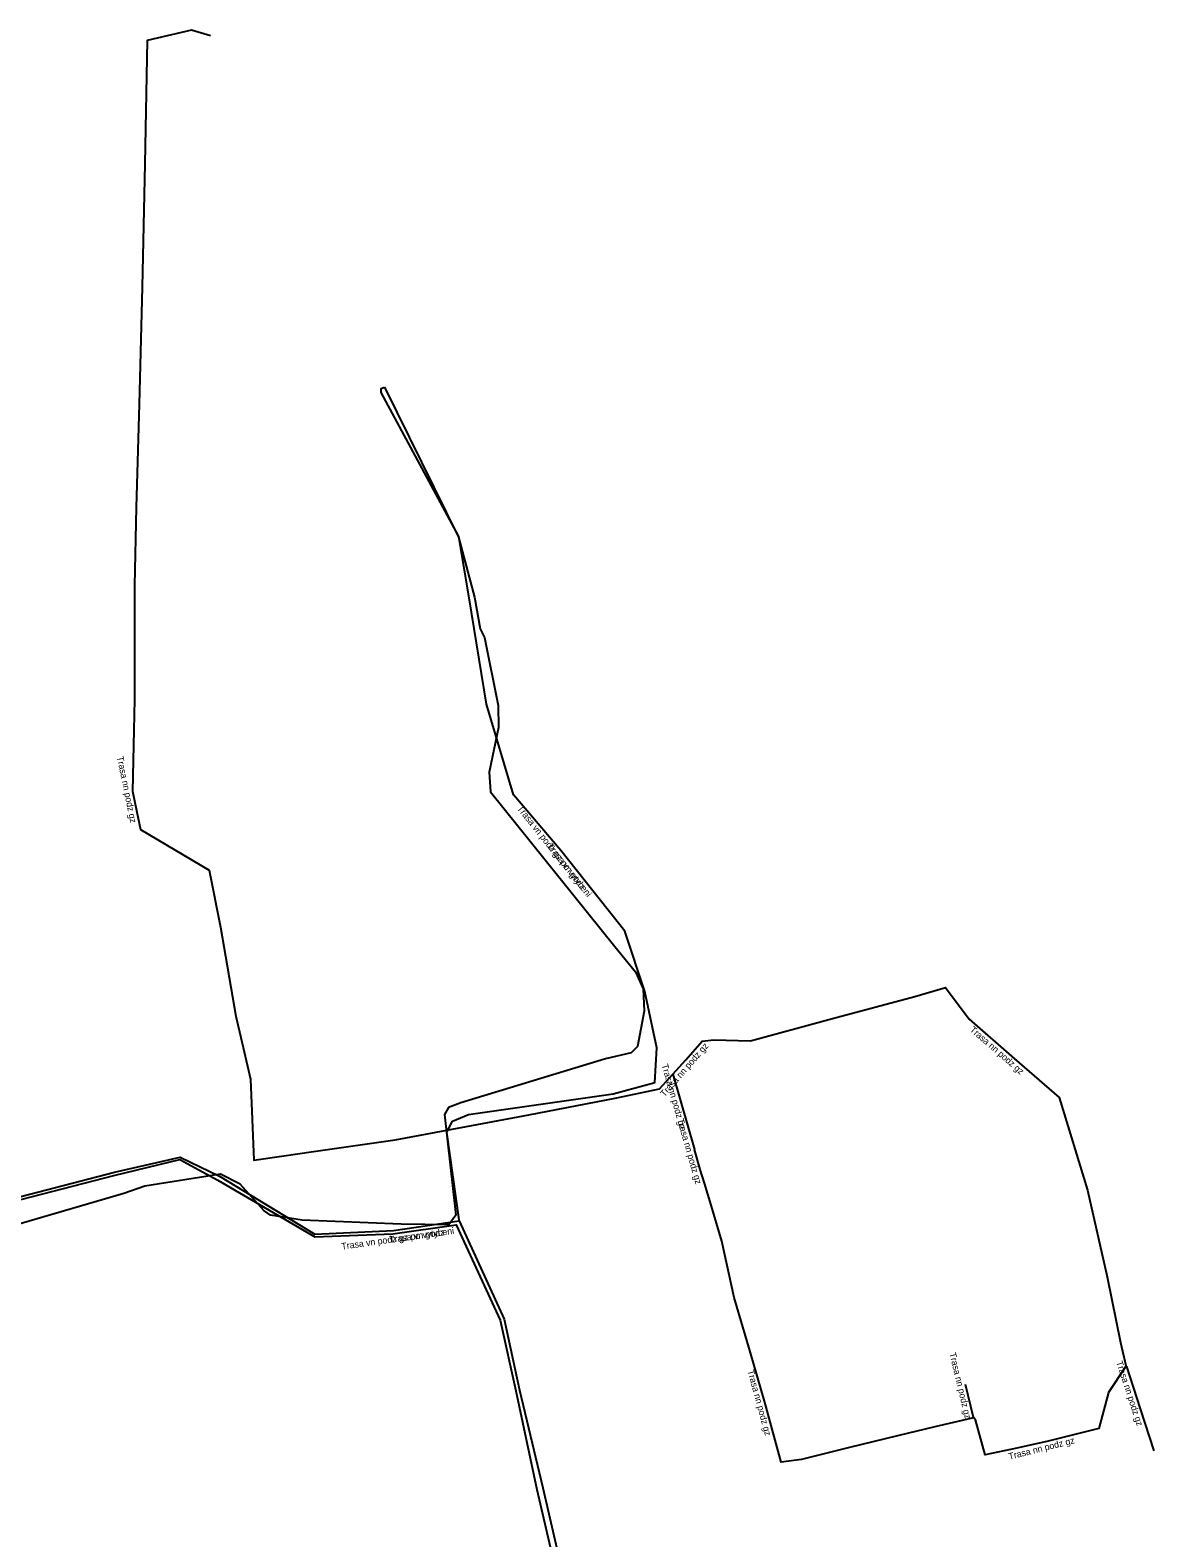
# Model space of a CAD drawing. Extents: x -473162 to -472638, y -1107075 to -1106812.
# Drawn here: x -472955.2 to -472870, y -1106926.5 to -1106811.6 of the extents above; entities that cross this region are included whole.
import ezdxf

# ---------------------------------------------------------------- set-up
doc = ezdxf.new("R2010")
doc.units = 0
for name, color, linetype in [('Popiskový text - Ostatní atributy Trasy', 7, 'Continuous'), ('Spojnice NN', 7, 'Continuous'), ('Spojnice VN', 7, 'Continuous')]:
    doc.layers.add(name, color=color, linetype=linetype)

msp = doc.modelspace()

# ---------------------------------------------------------------- linework, layer by layer
at = {"layer": 'Spojnice NN'}
for points in [[(-472941.42, -1106812.04), (-472942.88, -1106811.61), (-472946.26, -1106812.4), (-472946.45, -1106821.79), (-472946.64, -1106831.18), (-472946.88, -1106840.1), (-472947.11, -1106847.97), (-472947.23, -1106853.92), (-472947.23, -1106862.6), (-472947.3, -1106866.1), (-472947.37, -1106869.59), (-472947.07, -1106871.05), (-472946.78, -1106872.51), (-472944.16, -1106874.05), (-472941.54, -1106875.6), (-472940.66, -1106879.94), (-472939.5, -1106886.74), (-472938.94, -1106889.13), (-472938.38, -1106891.53), (-472938.26, -1106894.61), (-472938.14, -1106897.7), (-472935.85, -1106897.37), (-472933.57, -1106897.04), (-472927.37, -1106896.14), (-472917.16, -1106894.26), (-472910.59, -1106892.99), (-472907.22, -1106892.26), (-472906.19, -1106891.14)], [(-472903.07, -1106888.54), (-472900.28, -1106888.6), (-472894.02, -1106886.91), (-472887.75, -1106885.22), (-472885.42, -1106884.55), (-472883.6, -1106886.97), (-472880.17, -1106889.95), (-472876.75, -1106892.92), (-472874.59, -1106899.99), (-472873.09, -1106906.58), (-472872.07, -1106911.58), (-472871.66, -1106913.34)], [(-472906.19, -1106891.14), (-472905.21, -1106890.06), (-472903.96, -1106888.63), (-472903.07, -1106888.54)], [(-472906.19, -1106891.14), (-472904.55, -1106896.89)], [(-472903.79, -1106899.46), (-472904.11, -1106898.42), (-472904.55, -1106896.89)], [(-472883.28, -1106917.31), (-472883.39, -1106917.36), (-472886.23, -1106918.03), (-472889.08, -1106918.7), (-472892.73, -1106919.6), (-472896.39, -1106920.51), (-472897.94, -1106920.71), (-472899.16, -1106916.23), (-472900.34, -1106912.2), (-472901.53, -1106908.17), (-472902.46, -1106903.86), (-472903.28, -1106901.14), (-472903.79, -1106899.46)], [(-472871.66, -1106913.34), (-472871.7, -1106913.45), (-472872.98, -1106915.41), (-472873.73, -1106918.14), (-472875.67, -1106918.63), (-472877.6, -1106919.12), (-472879.99, -1106919.64), (-472882.38, -1106920.16), (-472883.12, -1106917.49), (-472883.28, -1106917.31)], [(-472871.66, -1106913.34), (-472871.62, -1106913.43), (-472870.58, -1106916.64), (-472869.53, -1106919.84)], [(-472883.28, -1106917.31), (-472883.88, -1106914.8)]]:
    msp.add_lwpolyline(points, dxfattribs=at)
at = {"layer": 'Spojnice VN'}
for points in [[(-472928.16, -1106838.82), (-472922.52, -1106850.25), (-472921.32, -1106854.81), (-472920.87, -1106857.23), (-472920.56, -1106857.88), (-472919.51, -1106863.05), (-472919.48, -1106864.74), (-472920.2, -1106868.15), (-472920.08, -1106869.65), (-472910.62, -1106881.43), (-472909.03, -1106883.35), (-472908.46, -1106884.65), (-472908.37, -1106886.35), (-472908.9, -1106889.03), (-472909.38, -1106889.53), (-472911.32, -1106889.98), (-472922.36, -1106893.33), (-472923.3, -1106893.7), (-472923.6, -1106894.23), (-472922.74, -1106901.9), (-472923.27, -1106902.63), (-472926.91, -1106902.58), (-472934.44, -1106902.26), (-472936.86, -1106901.89), (-472937.36, -1106901.54), (-472939.18, -1106899.52), (-472940.67, -1106898.78), (-472946.44, -1106899.69), (-472948.05, -1106900.25), (-472988.66, -1106912.1)], [(-472922.47, -1106902.33), (-472922.47, -1106902.24), (-472923.42, -1106895.58), (-472923, -1106894.72), (-472921.77, -1106894.21), (-472910.74, -1106892.66), (-472907.57, -1106891.79), (-472907.42, -1106889.15), (-472908.32, -1106884.84), (-472909.86, -1106880.26), (-472914.74, -1106874.11), (-472918.34, -1106869.87), (-472920.39, -1106862.95), (-472921.71, -1106854.87), (-472922.51, -1106850.19), (-472928.43, -1106839.21), (-472928.43, -1106838.91), (-472928.16, -1106838.82)], [(-472922.47, -1106902.33), (-472922.47, -1106902.24), (-472923.42, -1106895.58), (-472923, -1106894.72), (-472921.77, -1106894.21), (-472910.74, -1106892.66), (-472907.57, -1106891.79), (-472907.42, -1106889.15), (-472908.32, -1106884.84), (-472909.86, -1106880.26), (-472914.74, -1106874.11), (-472918.34, -1106869.87), (-472920.39, -1106862.95), (-472921.71, -1106854.87), (-472922.51, -1106850.19), (-472928.43, -1106839.21), (-472928.43, -1106838.91), (-472928.16, -1106838.82)], [(-472995.1, -1106913.58), (-472995.09, -1106913.64), (-472991.82, -1106912.59), (-472989.39, -1106911.45), (-472987.65, -1106910.69), (-472975.73, -1106906.39), (-472967.1, -1106902.9), (-472959.13, -1106901.32), (-472948.75, -1106898.61), (-472943.74, -1106897.47), (-472940.74, -1106898.91), (-472933.47, -1106903.33), (-472927.49, -1106903.06), (-472922.47, -1106902.33)], [(-472995.1, -1106913.58), (-472995.09, -1106913.64), (-472991.82, -1106912.59), (-472989.39, -1106911.45), (-472987.65, -1106910.69), (-472975.73, -1106906.39), (-472967.1, -1106902.9), (-472959.13, -1106901.32), (-472948.75, -1106898.61), (-472943.74, -1106897.47), (-472940.74, -1106898.91), (-472933.47, -1106903.33), (-472927.49, -1106903.06), (-472922.47, -1106902.33)], [(-472959.07, -1106901.51), (-472948.71, -1106898.85), (-472943.76, -1106897.66), (-472940.88, -1106899.23), (-472933.49, -1106903.53), (-472927.53, -1106903.31), (-472922.71, -1106902.64), (-472919.35, -1106909.88), (-472918.15, -1106915.27), (-472916.55, -1106922.8), (-472907.68, -1106960.98)], [(-472959.07, -1106901.51), (-472948.71, -1106898.85), (-472943.76, -1106897.66), (-472940.88, -1106899.23), (-472933.49, -1106903.53), (-472927.53, -1106903.31), (-472922.71, -1106902.64), (-472919.35, -1106909.88), (-472918.15, -1106915.27), (-472916.55, -1106922.8), (-472907.68, -1106960.98)], [(-472922.47, -1106902.33), (-472919.06, -1106909.81), (-472917.89, -1106915.23), (-472916.11, -1106922.66), (-472907.28, -1106960.88), (-472902.51, -1106980.47), (-472896.93, -1107003.41), (-472894.77, -1107013.03), (-472893.17, -1107018.95), (-472891.83, -1107024.39)], [(-472922.47, -1106902.33), (-472919.06, -1106909.81), (-472917.89, -1106915.23), (-472916.11, -1106922.66), (-472907.28, -1106960.88), (-472902.51, -1106980.47), (-472896.93, -1107003.41), (-472894.77, -1107013.03), (-472893.17, -1107018.95), (-472891.83, -1107024.39)]]:
    msp.add_lwpolyline(points, dxfattribs=at)

# ---------------------------------------------------------------- texts
at = {"layer": 'Popiskový text - Ostatní atributy Trasy'}
for s, rotation, p in [('Trasa nn podz gz', 281.5593, (-472948.57, -1106866.98)), ('Trasa vn podz gz po vytyceni', 308.4309, (-472918.1, -1106870.92)), ('Trasa vn podz', 308.4309, (-472915.81, -1106873.81)), ('Trasa nn podz gz', 319.0125, (-472883.6, -1106887.83)), ('Trasa nn podz gz', 48.9817, (-472906.83, -1106892.92)), ('Trasa nn podz gz', 285.9444, (-472907.06, -1106890.45)), ('Trasa nn podz gz', 285.9392, (-472905.87, -1106894.61)), ('Trasa vn podz gz po vytyceni', 8.0434, (-472931.42, -1106904.52)), ('Trasa vn podz', 8.0434, (-472927.77, -1106904.01)), ('Trasa nn podz gz', 283.4439, (-472885.12, -1106912.42)), ('Trasa nn podz gz', 285.2173, (-472900.51, -1106913.75)), ('Trasa nn podz gz', 288.1501, (-472872.42, -1106913.09)), ('Trasa nn podz gz', 14.2307, (-472880.54, -1106920.53))]:
    msp.add_text(s, height=0.5, rotation=rotation, dxfattribs=at).set_placement(p)

doc.saveas('drawing.dxf')
